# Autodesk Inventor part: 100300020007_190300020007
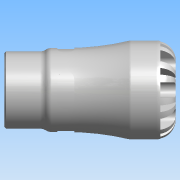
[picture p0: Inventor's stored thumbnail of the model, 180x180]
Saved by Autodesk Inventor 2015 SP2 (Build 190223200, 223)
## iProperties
Created: 2016-12
Part Number: 100300020007_190300020007
Material: PVC-Piping
Description: PLASSON FEMALE ADAPTOR 20X3/4" SERIES 1
Document SubType Name: Modeling
Designer: KIM
Mass: 664.223 g
Surface Area: 733.008 cm^2
Volume: 474.445 cm^3
Density: 1.4 g/cm^3
Appearance: Smooth - White
Author: KIM
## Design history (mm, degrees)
derived "1003.ipt"
feature "Solid1::1003.ipt"
tag "TaggingFeature1"
body "Solid1"
other parameters: "d0" = 71, "d1" = 18.9, "d3" = 25, "d4" = 41, "d6" = 45, "d8" = 34.85, "d13" = 6.4, "d14" = 6.4, "d15" = 0, "d17" = 360 deg, "d19" = 8 deg, "d20" = 0.4, "d21" = 0.4, "d22" = 8 deg, "d24" = 0, "d26" = 360 deg, "d32" = 4.1, "d33" = 4.1, "d39" = 0.72351, "d42" = 24.117, "d43" = 31.98, "d46" = 1.66667, "d47" = 18, "d48" = 22.91115, "d50" = 2.64, "d51" = 0.41, "d54" = 7, "d55" = 4.4, "d57" = 12.544, "d58" = 0, "d68" = 360 deg, "d72" = 0.4, "d74" = 0, "d76" = 5.95, "E_" = 41, "H_" = 71, "l_" = 45, "Rp" = 24.117, "l_2" = 18, "d9" = 8, "d11" = 41, "d12" = 25, "d49" = 8
